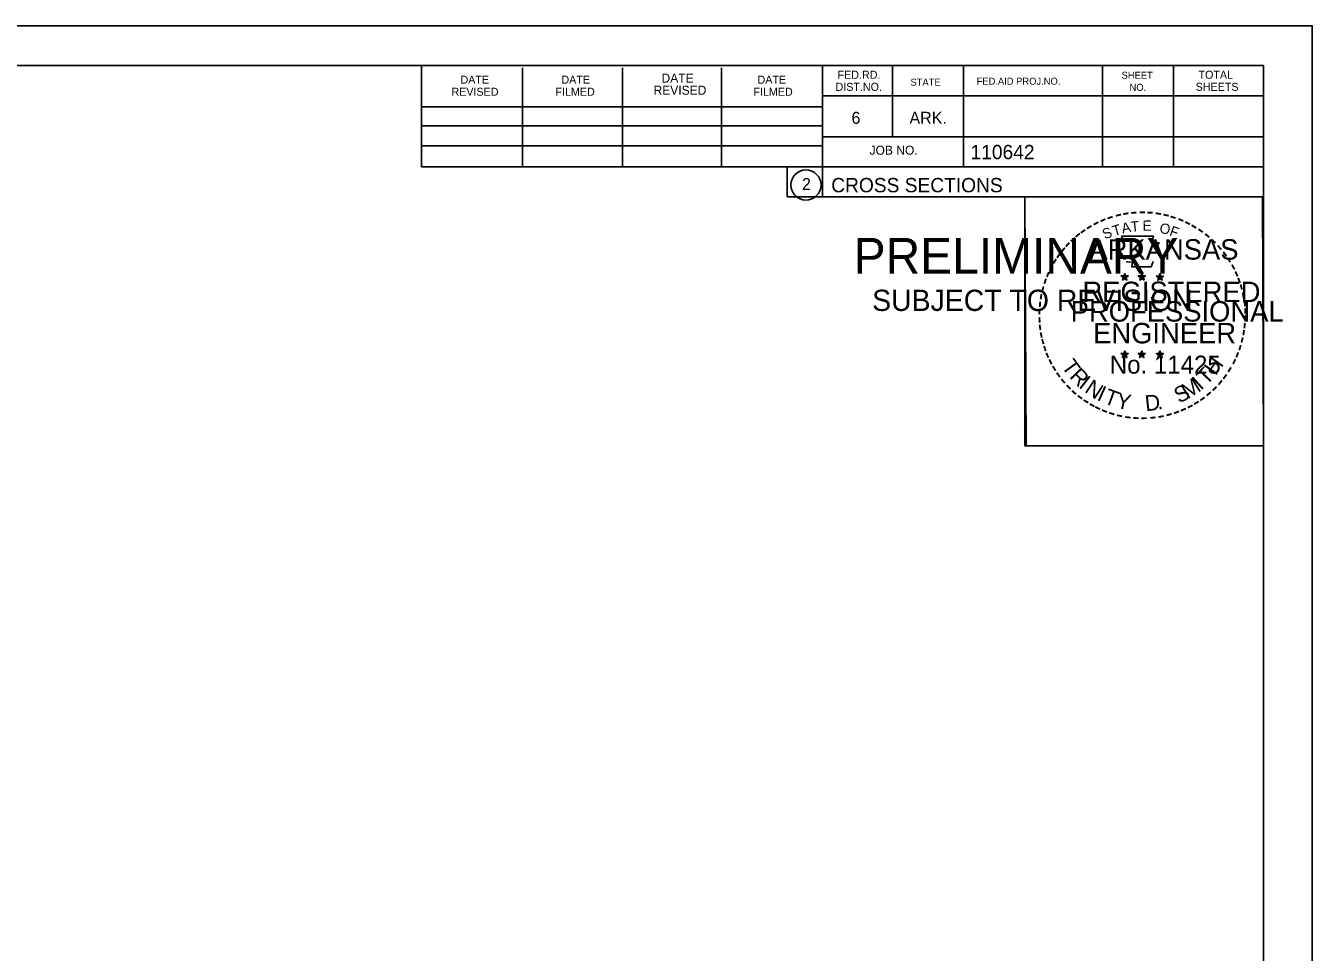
# Model space of a CAD drawing. Extents: x 1368503 to 1373085, y 379840 to 381833.
# Drawn here: x 1368710.3 to 1368836, y 380675.6 to 380766.1 of the extents above; entities that cross this region are included whole.
import ezdxf

# ---------------------------------------------------------------- set-up
doc = ezdxf.new("R2010")
doc.units = 0
for name, color, linetype in [('S_BRIDGE', 7, 'Continuous'), ('S_LANDSCAPING', 7, 'Continuous'), ('S_MISC_BOUNDARY_ANNOT', 7, 'Continuous'), ('S_PHOTO_NOTES', 7, 'Continuous')]:
    doc.layers.add(name, color=color, linetype=linetype)

msp = doc.modelspace()

# ---------------------------------------------------------------- linework, layer by layer
at = {"layer": 'S_BRIDGE'}
for p, q in [((1368515.06, 380762.16), (1368831.24, 380762.16)), ((1368748.98, 380752.28), (1368748.98, 380762.16)), ((1368758.84, 380752.28), (1368758.84, 380761.96)), ((1368768.6, 380752.28), (1368768.6, 380761.96)), ((1368778.28, 380752.28), (1368778.28, 380761.96)), ((1368788.14, 380762.16), (1368788.14, 380749.36)), ((1368794.98, 380762.16), (1368794.98, 380755.22)), ((1368801.92, 380762.16), (1368801.92, 380752.28)), ((1368815.5, 380762.16), (1368815.5, 380752.28)), ((1368822.44, 380762.16), (1368822.44, 380752.28)), ((1368831.24, 380556.7), (1368831.24, 380762.16)), ((1368748.98, 380758.14), (1368788.14, 380758.14)), ((1368831.24, 380759.22), (1368788.14, 380759.22)), ((1368831.24, 380759.24), (1368831.24, 380759.24)), ((1368748.98, 380756.28), (1368788.14, 380756.28)), ((1368748.98, 380752.28), (1368748.98, 380754.34)), ((1368748.98, 380754.34), (1368788.14, 380754.34)), ((1368831.24, 380755.22), (1368788.14, 380755.22)), ((1368791.1, 380755.22), (1368831.24, 380755.22)), ((1368831.24, 380752.28), (1368748.98, 380752.28)), ((1368788.14, 380749.36), (1368831.24, 380749.36))]:
    msp.add_line(p, q, dxfattribs=at)
msp.add_circle((1368786.53, 380750.5), 1.47, dxfattribs=at)
at = {"layer": 'S_LANDSCAPING'}
for p, q in [((1368817.67, 380741.87), (1368817.63, 380741.62)), ((1368817.67, 380741.51), (1368817.67, 380741.87)), ((1368817.67, 380741.87), (1368817.72, 380741.62)), ((1368819.34, 380741.87), (1368819.3, 380741.62)), ((1368819.34, 380741.51), (1368819.34, 380741.87)), ((1368819.34, 380741.87), (1368819.39, 380741.62)), ((1368821.11, 380741.86), (1368821.07, 380741.61)), ((1368821.11, 380741.5), (1368821.11, 380741.86)), ((1368821.11, 380741.86), (1368821.16, 380741.61)), ((1368817.32, 380741.62), (1368817.67, 380741.51)), ((1368817.32, 380741.62), (1368817.58, 380741.57)), ((1368817.32, 380741.62), (1368817.56, 380741.5)), ((1368817.46, 380741.21), (1368817.67, 380741.51)), ((1368817.46, 380741.21), (1368817.58, 380741.46)), ((1368817.46, 380741.21), (1368817.67, 380741.43)), ((1368818.02, 380741.62), (1368817.67, 380741.51)), ((1368817.89, 380741.21), (1368817.67, 380741.51)), ((1368817.89, 380741.21), (1368817.67, 380741.43)), ((1368818.02, 380741.62), (1368817.73, 380741.57)), ((1368817.89, 380741.21), (1368817.75, 380741.5)), ((1368818.02, 380741.62), (1368817.82, 380741.52)), ((1368818.99, 380741.62), (1368819.34, 380741.51)), ((1368818.99, 380741.62), (1368819.25, 380741.57)), ((1368818.99, 380741.62), (1368819.23, 380741.5)), ((1368819.13, 380741.21), (1368819.34, 380741.51)), ((1368819.13, 380741.21), (1368819.25, 380741.46)), ((1368819.13, 380741.21), (1368819.34, 380741.43)), ((1368819.69, 380741.62), (1368819.34, 380741.51)), ((1368819.56, 380741.21), (1368819.34, 380741.51)), ((1368819.56, 380741.21), (1368819.34, 380741.43)), ((1368819.69, 380741.62), (1368819.4, 380741.57)), ((1368819.56, 380741.21), (1368819.42, 380741.5)), ((1368819.69, 380741.62), (1368819.49, 380741.52)), ((1368820.76, 380741.61), (1368821.11, 380741.5)), ((1368820.76, 380741.61), (1368821.01, 380741.56)), ((1368820.76, 380741.61), (1368820.99, 380741.49)), ((1368820.89, 380741.2), (1368821.11, 380741.5)), ((1368820.89, 380741.2), (1368821.02, 380741.44)), ((1368820.89, 380741.2), (1368821.1, 380741.42)), ((1368821.32, 380741.2), (1368821.1, 380741.41)), ((1368821.45, 380741.61), (1368821.11, 380741.5)), ((1368821.32, 380741.2), (1368821.11, 380741.5)), ((1368821.45, 380741.61), (1368821.17, 380741.56)), ((1368821.32, 380741.2), (1368821.18, 380741.49)), ((1368821.45, 380741.61), (1368821.25, 380741.51)), ((1368817.67, 380734.3), (1368817.63, 380734.05)), ((1368817.67, 380733.94), (1368817.67, 380734.3)), ((1368817.67, 380734.3), (1368817.72, 380734.05)), ((1368819.34, 380734.3), (1368819.3, 380734.05)), ((1368819.34, 380733.94), (1368819.34, 380734.3)), ((1368819.34, 380734.3), (1368819.39, 380734.05)), ((1368821.1, 380734.29), (1368821.06, 380734.04)), ((1368821.1, 380733.93), (1368821.1, 380734.29)), ((1368821.1, 380734.29), (1368821.15, 380734.04)), ((1368817.32, 380734.05), (1368817.67, 380733.94)), ((1368817.32, 380734.05), (1368817.57, 380734)), ((1368817.32, 380734.05), (1368817.56, 380733.92)), ((1368817.45, 380733.64), (1368817.67, 380733.94)), ((1368817.45, 380733.64), (1368817.58, 380733.88)), ((1368817.45, 380733.64), (1368817.67, 380733.86)), ((1368818.02, 380734.05), (1368817.67, 380733.94)), ((1368817.88, 380733.64), (1368817.67, 380733.94)), ((1368817.88, 380733.64), (1368817.67, 380733.85)), ((1368818.02, 380734.05), (1368817.73, 380734)), ((1368817.88, 380733.64), (1368817.74, 380733.93)), ((1368818.02, 380734.05), (1368817.81, 380733.94)), ((1368818.99, 380734.05), (1368819.34, 380733.94)), ((1368818.99, 380734.05), (1368819.24, 380734)), ((1368818.99, 380734.05), (1368819.23, 380733.92)), ((1368819.12, 380733.64), (1368819.34, 380733.94)), ((1368819.12, 380733.64), (1368819.25, 380733.88)), ((1368819.12, 380733.64), (1368819.34, 380733.86)), ((1368819.68, 380734.05), (1368819.34, 380733.94)), ((1368819.55, 380733.64), (1368819.34, 380733.94)), ((1368819.55, 380733.64), (1368819.34, 380733.85)), ((1368819.68, 380734.05), (1368819.4, 380734)), ((1368819.55, 380733.64), (1368819.41, 380733.93)), ((1368819.68, 380734.05), (1368819.48, 380733.94)), ((1368820.76, 380734.04), (1368821.1, 380733.93)), ((1368820.76, 380734.04), (1368821.01, 380733.99)), ((1368820.76, 380734.04), (1368820.99, 380733.91)), ((1368820.89, 380733.63), (1368821.1, 380733.93)), ((1368820.89, 380733.63), (1368821.01, 380733.87)), ((1368820.89, 380733.63), (1368821.1, 380733.85)), ((1368821.45, 380734.04), (1368821.1, 380733.93)), ((1368821.32, 380733.63), (1368821.1, 380733.93)), ((1368821.32, 380733.63), (1368821.1, 380733.84)), ((1368821.45, 380734.04), (1368821.17, 380733.99)), ((1368821.32, 380733.63), (1368821.18, 380733.92)), ((1368821.45, 380734.04), (1368821.25, 380733.93))]:
    msp.add_line(p, q, dxfattribs=at)
for points in [[(1368817.36, 380745.5), (1368817.63, 380744.67)], [(1368820.88, 380744.58), (1368821.02, 380744.86), (1368820.33, 380744.84), (1368820.48, 380745.5), (1368817.36, 380745.5)], [(1368817.86, 380743.07), (1368817.86, 380742.99), (1368818.42, 380742.97), (1368818.37, 380742.5), (1368820.24, 380742.5), (1368820.44, 380743.03)], [(1368817.67, 380741.87), (1368817.89, 380741.21), (1368817.32, 380741.62), (1368818.02, 380741.62), (1368817.46, 380741.21), (1368817.67, 380741.87)], [(1368819.34, 380741.87), (1368819.56, 380741.21), (1368818.99, 380741.62), (1368819.69, 380741.62), (1368819.13, 380741.21), (1368819.34, 380741.87)], [(1368821.11, 380741.86), (1368821.32, 380741.2), (1368820.76, 380741.61), (1368821.45, 380741.61), (1368820.89, 380741.2), (1368821.11, 380741.86)], [(1368817.67, 380734.3), (1368817.88, 380733.64), (1368817.32, 380734.05), (1368818.02, 380734.05), (1368817.45, 380733.64), (1368817.67, 380734.3)], [(1368819.34, 380734.3), (1368819.55, 380733.64), (1368818.99, 380734.05), (1368819.68, 380734.05), (1368819.12, 380733.64), (1368819.34, 380734.3)], [(1368821.1, 380734.29), (1368821.32, 380733.63), (1368820.76, 380734.04), (1368821.45, 380734.04), (1368820.89, 380733.63), (1368821.1, 380734.29)]]:
    msp.add_lwpolyline(points, dxfattribs=at)
for centre, radius in [((1368817.67, 380741.51), 0.172), ((1368817.67, 380741.51), 0.145), ((1368817.67, 380741.51), 0.116), ((1368817.67, 380741.51), 0.0991), ((1368817.67, 380741.51), 0.0747), ((1368817.67, 380741.51), 0.0495), ((1368817.67, 380741.51), 0.0296), ((1368819.34, 380741.51), 0.172), ((1368819.34, 380741.51), 0.145), ((1368819.34, 380741.51), 0.116), ((1368819.34, 380741.51), 0.0991), ((1368819.34, 380741.51), 0.0747), ((1368819.34, 380741.51), 0.0495), ((1368819.34, 380741.51), 0.0296), ((1368821.11, 380741.5), 0.172), ((1368821.11, 380741.5), 0.145), ((1368821.11, 380741.5), 0.116), ((1368821.11, 380741.5), 0.0991), ((1368821.11, 380741.5), 0.0747), ((1368821.11, 380741.5), 0.0495), ((1368821.11, 380741.5), 0.0296), ((1368817.67, 380733.93), 0.172), ((1368817.67, 380733.93), 0.145), ((1368817.67, 380733.93), 0.116), ((1368817.67, 380733.93), 0.0991), ((1368817.67, 380733.93), 0.0747), ((1368817.67, 380733.93), 0.0495), ((1368817.67, 380733.93), 0.0296), ((1368819.34, 380733.93), 0.172), ((1368819.34, 380733.93), 0.145), ((1368819.34, 380733.93), 0.116), ((1368819.34, 380733.93), 0.0991), ((1368819.34, 380733.93), 0.0747), ((1368819.34, 380733.93), 0.0495), ((1368819.34, 380733.93), 0.0296), ((1368821.1, 380733.92), 0.172), ((1368821.1, 380733.92), 0.145), ((1368821.1, 380733.92), 0.116), ((1368821.1, 380733.92), 0.0991), ((1368821.1, 380733.92), 0.0747), ((1368821.1, 380733.92), 0.0495), ((1368821.1, 380733.92), 0.0296)]:
    msp.add_circle(centre, radius, dxfattribs=at)
at = {"layer": 'S_PHOTO_NOTES'}
for p, q in [((1368502.66, 380766.06), (1368835.99, 380766.06)), ((1368807.27, 380726.91), (1368807.27, 380726.91))]:
    msp.add_line(p, q, dxfattribs=at)
for points in [[(1368502.65, 380766.06), (1368835.99, 380766.06), (1368835.99, 380552.72), (1368502.65, 380552.72)], [(1368748.98, 380762.16), (1368748.98, 380752.28), (1368784.71, 380752.28), (1368784.71, 380749.36), (1368807.91, 380749.36), (1368807.91, 380725.03), (1368831.24, 380725.03), (1368831.24, 380556.7), (1368515.06, 380556.7), (1368515.06, 380762.16)], [(1368807.91, 380749.36), (1368831.12, 380749.36), (1368831.24, 380725.03), (1368808.03, 380725.03)]]:
    msp.add_lwpolyline(points, close=True, dxfattribs=at)

# ---------------------------------------------------------------- texts
at = {"layer": 'S_BRIDGE'}
for s, height, p in [('DATE', 0.782, (1368752.78, 380760.4)), ('DATE', 0.782, (1368762.64, 380760.4)), ('DATE', 0.879, (1368772.42, 380760.5)), ('DATE', 0.782, (1368781.8, 380760.4)), ('FED.RD.', 0.782, (1368789.62, 380760.88)), ('STATE', 0.684, (1368796.74, 380760.2)), ('FED.AID PROJ.NO.', 0.684, (1368803.2, 380760.3)), ('SHEET', 0.684, (1368817.36, 380760.88)), ('TOTAL', 0.782, (1368824.88, 380760.88)), ('REVISED', 0.782, (1368751.9, 380759.22)), ('FILMED', 0.782, (1368762.06, 380759.22)), ('REVISED', 0.879, (1368771.64, 380759.32)), ('FILMED', 0.782, (1368781.4, 380759.22)), ('DIST.NO.', 0.782, (1368789.42, 380759.7)), ('NO.', 0.684, (1368818.14, 380759.7)), ('SHEETS', 0.782, (1368824.6, 380759.7)), ('6', 1.17, (1368790.98, 380756.48)), ('ARK.', 1.172, (1368796.64, 380756.48)), ('JOB NO.', 0.879, (1368792.74, 380753.46)), ('110642', 1.4, (1368802.61, 380753.02)), ('2', 1.17, (1368786.14, 380750.01)), ('CROSS SECTIONS', 1.4, (1368789, 380749.79))]:
    msp.add_text(s, height=height, rotation=360, dxfattribs=at).set_placement(p)
at = {"layer": 'S_LANDSCAPING'}
for s, height, rotation, p in [('-', 1.6, 28.7918, (1368814.85, 380746.04)), ('-', 1.6, 24.3072, (1368815.48, 380746.36)), ('-', 1.6, 19.1761, (1368816.11, 380746.62)), ('-', 1.6, 13.6301, (1368816.86, 380746.87)), ('A', 1, 11.2132, (1368817.46, 380745.76)), ('-', 1.6, 10.2193, (1368817.54, 380747.03)), ('T', 1, 6.0228, (1368818.31, 380745.92)), ('-', 1.6, 5.8968, (1368818.27, 380747.14)), ('-', 1.6, 0.1862, (1368819.04, 380747.21)), ('E', 1, 0.8323, (1368819.41, 380746.03)), ('-', 1.6, 357.743, (1368819.76, 380747.2)), ('-', 1.6, 352.1617, (1368820.51, 380747.14)), ('-', 1.6, 347.2049, (1368821.23, 380747.03)), ('-', 1.6, 342.3362, (1368821.86, 380746.87)), ('-', 1.6, 337.8551, (1368822.6, 380746.65)), ('-', 1.6, 334.1211, (1368823.23, 380746.38)), ('-', 1.6, 38.9507, (1368813.19, 380744.9)), ('-', 1.6, 36.2317, (1368813.67, 380745.27)), ('-', 1.6, 34.0636, (1368814.25, 380745.67)), ('S', 1, 21.594, (1368815.72, 380745.18)), ('T', 1, 16.4036, (1368816.63, 380745.51)), ('O', 1, 350.4515, (1368821.02, 380745.82)), ('F', 1, 340.0707, (1368821.97, 380745.6)), ('-', 1.6, 329.6409, (1368823.81, 380746.09)), ('-', 1.6, 325.8627, (1368824.45, 380745.73)), ('-', 1.6, 320.5297, (1368825.06, 380745.31)), ('-', 1.6, 50.6142, (1368811.91, 380743.51)), ('-', 1.6, 48.423, (1368812.31, 380744)), ('-', 1.6, 42.9622, (1368812.76, 380744.48)), ('ARKANSAS', 2, 360, (1368814.22, 380743.21)), ('-', 1.6, 315.5786, (1368825.66, 380744.82)), ('-', 1.6, 309.8797, (1368826.23, 380744.27)), ('-', 1.6, 58.0706, (1368811.17, 380742.42)), ('-', 1.6, 54.2325, (1368811.5, 380742.95)), ('-', 1.6, 306.6522, (1368826.75, 380743.67)), ('-', 1.4, 303.6753, (1368827.24, 380743.1)), ('-', 1.6, 67.7743, (1368810.6, 380741.2)), ('-', 1.6, 62.8713, (1368810.86, 380741.81)), ('-', 1.6, 299.6684, (1368827.56, 380742.49)), ('-', 1.6, 294.6628, (1368827.88, 380741.88)), ('-', 1.6, 75.461, (1368810.18, 380739.85)), ('-', 1.6, 72.3945, (1368810.38, 380740.57)), ('REGISTERED', 2, 360, (1368813.54, 380739.06)), ('DWB', 0.01, 360, (1368817.66, 380741.5)), ('DWB', 0.01, 360, (1368819.33, 380741.5)), ('DWB', 0.01, 360, (1368821.09, 380741.49)), ('-', 1.6, 290.5728, (1368828.14, 380741.3)), ('-', 1.6, 285.1233, (1368828.37, 380740.72)), ('-', 1.6, 81.2013, (1368810.05, 380739.14)), ('-', 1.6, 280.5493, (1368828.57, 380739.98)), ('-', 1.6, 89.0622, (1368809.95, 380737.75)), ('-', 1.6, 85.1863, (1368809.98, 380738.45)), ('PROFESSIONAL', 2, 360, (1368812.39, 380737.16)), ('-', 1.6, 276.5962, (1368828.74, 380739.21)), ('-', 1.6, 274.3301, (1368828.8, 380738.49)), ('-', 1.6, 94.1959, (1368809.99, 380737.02)), ('-', 1.6, 98.9479, (1368810.06, 380736.35)), ('ENGINEER', 2, 360, (1368814.58, 380735.03)), ('-', 1.6, 263.5172, (1368828.81, 380737.19)), ('-', 1.6, 269.9407, (1368828.83, 380737.86)), ('-', 1.6, 101.7149, (1368810.19, 380735.62)), ('-', 1.6, 105.4578, (1368810.36, 380735.03)), ('-', 1.6, 255.7626, (1368828.63, 380735.86)), ('-', 1.6, 260.9953, (1368828.74, 380736.54)), ('-', 1.6, 109.0874, (1368810.57, 380734.4)), ('-', 1.6, 252.8681, (1368828.45, 380735.14)), ('-', 1.6, 114.0643, (1368810.82, 380733.8)), ('-', 1.6, 115.7289, (1368811.13, 380733.18)), ('T', 1.54, 306.0406, (1368811.43, 380732.77)), ('No. 11425', 1.757, 360, (1368816.21, 380732.08)), ('DWB', 0.01, 360, (1368817.66, 380733.93)), ('DWB', 0.01, 360, (1368819.33, 380733.93)), ('DWB', 0.01, 360, (1368821.09, 380733.92)), ('H', 1.54, 54.6088, (1368826.55, 380731.81)), ('-', 1.6, 244.6197, (1368827.96, 380733.84)), ('-', 1.6, 247.8887, (1368828.23, 380734.47)), ('-', 1.6, 120.4471, (1368811.49, 380732.6)), ('-', 1.6, 125.8934, (1368811.89, 380732.03)), ('R', 1.54, 314.005, (1368812.19, 380731.73)), ('I', 1.54, 321.9694, (1368813.09, 380730.79)), ('I', 1.54, 42.1136, (1368825.1, 380730.39)), ('T', 1.54, 46.6444, (1368825.66, 380730.87)), ('-', 1.6, 233.8452, (1368827.17, 380732.43)), ('-', 1.6, 239.0712, (1368827.57, 380733.09)), ('-', 1.6, 130.7181, (1368812.35, 380731.48)), ('-', 1.6, 134.2238, (1368812.87, 380730.94)), ('-', 1.6, 138.9338, (1368813.39, 380730.47)), ('N', 1.54, 326.5002, (1368813.66, 380730.32)), ('I', 1.54, 335.3603, (1368814.87, 380729.54)), ('T', 1.54, 339.8912, (1368815.53, 380729.21)), ('S', 1.54, 26.9312, (1368822.97, 380729.14)), ('M', 1.54, 32.6563, (1368823.81, 380729.54)), ('-', 1.6, 225.7653, (1368826.26, 380731.3)), ('-', 1.6, 231.2538, (1368826.74, 380731.87)), ('-', 1.6, 144.6463, (1368813.95, 380730.07)), ('-', 1.6, 148.0898, (1368814.51, 380729.7)), ('-', 1.6, 151.5704, (1368815.09, 380729.37)), ('Y', 1.54, 347.8556, (1368816.74, 380728.76)), ('D', 1.54, 6.3969, (1368819.73, 380728.4)), ('-', 1.6, 212.2491, (1368824.65, 380729.94)), ('-', 1.6, 215.7363, (1368825.19, 380730.32)), ('-', 1.6, 221.0851, (1368825.74, 380730.8)), ('-', 1.6, 154.6002, (1368815.61, 380729.12)), ('-', 1.6, 158.5612, (1368816.24, 380728.87)), ('-', 1.6, 162.7983, (1368816.92, 380728.66)), ('-', 1.6, 167.5555, (1368817.64, 380728.49)), ('-', 1.6, 173.1155, (1368818.41, 380728.38)), ('-', 1.6, 191.2858, (1368821.45, 380728.56)), ('.', 1.54, 13.7642, (1368820.92, 380728.53)), ('-', 1.6, 195.4743, (1368822.18, 380728.76)), ('-', 1.6, 200.7184, (1368822.85, 380729)), ('-', 1.6, 204.2516, (1368823.47, 380729.27)), ('-', 1.6, 207.3568, (1368824.1, 380729.59)), ('-', 1.6, 176.5183, (1368819.16, 380728.33)), ('-', 1.6, 181.5918, (1368819.9, 380728.35)), ('-', 1.6, 185.8167, (1368820.71, 380728.43))]:
    msp.add_text(s, height=height, rotation=rotation, dxfattribs=at).set_placement(p)
at = {"layer": 'S_MISC_BOUNDARY_ANNOT'}
for s, height, p in [('PRELIMINARY', 3.5, (1368791.19, 380741.83)), ('DWB', 0.01, (1368791.94, 380743.68)), ('SUBJECT TO REVISION', 2.0751, (1368793, 380738.2))]:
    msp.add_text(s, height=height, rotation=360, dxfattribs=at).set_placement(p)

doc.saveas('drawing.dxf')
